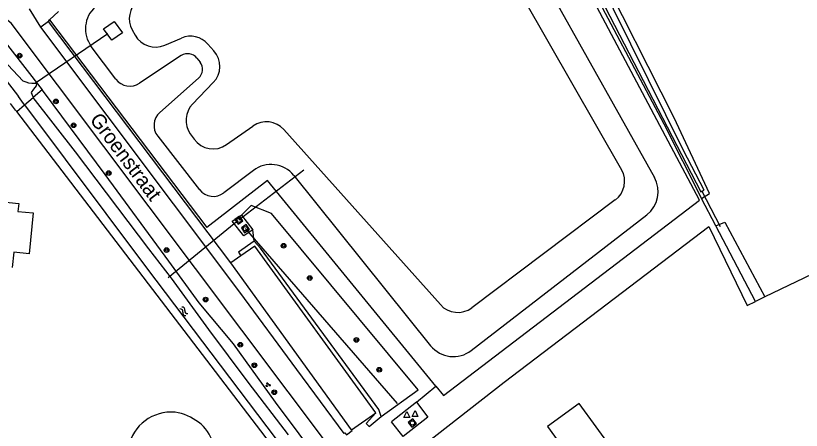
# Model space of a CAD drawing. Extents: x 136000 to 141014, y 402000 to 403500.
# Drawn here: x 137823.8 to 137958.3, y 402938.4 to 403009.4 of the extents above; entities that cross this region are included whole.
import ezdxf

# ---------------------------------------------------------------- set-up
doc = ezdxf.new("R2010")
doc.units = 0
for name, color, linetype in [('gg-afsc-hekwerk', 7, 'Continuous'), ('gg-anno-openbare ruimte label', 7, 'Continuous'), ('gg-bbg-gedigitaliseerde bijgebouw', 7, 'Continuous'), ('gg-bbg-hoofdgebouw', 7, 'Continuous'), ('gg-knt-bronhoudergrens', 7, 'Continuous'), ('gg-knt-verharding', 7, 'Continuous'), ('gg-knt-verharding nz', 7, 'Continuous'), ('gg-kntw-bovenkant insteek waterloop', 7, 'Continuous'), ('gg-kntw-waterlijn', 7, 'Continuous'), ('gg-kwrk-betonelement', 7, 'Continuous'), ('gg-kwrk-duiker nz buis', 7, 'Continuous'), ('gt-grn-groengrens', 7, 'Continuous'), ('gt-grn-vlakafsluiter', 7, 'Continuous'), ('gt-symb-boom', 7, 'Continuous'), ('gt-symb-groenvak', 7, 'Continuous'), ('gt-symb-rioolschacht', 7, 'Continuous'), ('gt-symb-waterafsluiter', 7, 'Continuous'), ('gt-symb-watersymbool', 7, 'Continuous'), ('gx-grn-maaiveld', 7, 'Continuous')]:
    doc.layers.add(name, color=color, linetype=linetype)

# ---------------------------------------------------------------- blocks, each defined once
blk = doc.blocks.new('gt0-RS')
at = {"layer": 'gt-symb-rioolschacht'}
blk.add_lwpolyline([(-0.5, -0.5), (0.5, -0.5), (0.5, 0.5), (-0.5, 0.5)], close=True, dxfattribs=at)
blk.add_circle((0, 0), 0.375, dxfattribs=at)
blk = doc.blocks.new('gt0-BOOM')
at = {"layer": 'gt-symb-boom'}
for radius in [0.4, 0.2]:
    blk.add_circle((0, 0), radius, dxfattribs=at)
blk = doc.blocks.new('gt0-WAFSL')
at = {"layer": 'gt-symb-waterafsluiter'}
for p, q in [((-0.5, -0.33), (0, 0.67)), ((0, 0.67), (0.5, -0.33)), ((0.5, -0.33), (-0.5, -0.33))]:
    blk.add_line(p, q, dxfattribs=at)
blk = doc.blocks.new('gt0-GRVAK')
at = {"layer": 'gt-symb-groenvak'}
for p, q in [((-0.11, 0.19), (-0.23, 0.24)), ((-0.18, 0.15), (0.09, 0.15)), ((-0.09, 0.21), (-0.16, 0.32)), ((-0.05, 0.21), (-0.05, 0.39)), ((0, 0.21), (0.06, 0.32)), ((0.02, 0.19), (0.13, 0.24)), ((0.26, -0.05), (0.2, 0.06)), ((0.31, -0.05), (0.31, 0.13)), ((0.35, -0.05), (0.41, 0.06)), ((-0.24, -0.23), (-0.36, -0.18)), ((-0.32, -0.26), (-0.05, -0.26)), ((-0.23, -0.21), (-0.29, -0.1)), ((-0.18, -0.2), (-0.18, -0.02)), ((-0.14, -0.21), (-0.07, -0.1)), ((-0.12, -0.23), (0, -0.18)), ((0.24, -0.07), (0.12, -0.02)), ((0.17, -0.11), (0.44, -0.11)), ((0.37, -0.07), (0.49, -0.02))]:
    blk.add_line(p, q, dxfattribs=at)
blk = doc.blocks.new('gt0-WA')
at = {"layer": 'gt-symb-watersymbool'}
for centre, start, end in [((-0.32, 0.02), 28.0725, 151.9275), ((0.43, 0.42), 208.0725, 331.9275), ((-0.32, -0.43), 28.0725, 151.9275), ((0.43, -0.03), 208.0725, 331.9275)]:
    blk.add_arc(centre, 0.425, start, end, dxfattribs=at)

msp = doc.modelspace()

# ---------------------------------------------------------------- linework, layer by layer
at = {"layer": 'gg-afsc-hekwerk'}
for p, q in [((137831.1, 403010.12), (137829.58, 403008.71)), ((137829.58, 403008.71), (137856.5, 402973.11)), ((137997.59, 402983.24), (137952.1, 402961.23))]:
    msp.add_line(p, q, dxfattribs=at)
for points in [[(137895.76, 402945.93), (137897.05, 402944.35), (137940.87, 402977.81), (137893.16, 403067.81), (137862.45, 403039.26)], [(137895.76, 402945.93), (137897.05, 402944.35), (137940.87, 402977.81), (137893.16, 403067.81)], [(137895.76, 402945.93), (137866.92, 402981.15), (137856.5, 402973.11)], [(137899.84, 402918.55), (137891.2, 402930.13), (137891.81, 402934.4), (137907.47, 402946.6), (137942.51, 402973.26), (137949.05, 402959.75), (137950.49, 402960.45)]]:
    msp.add_lwpolyline(points, dxfattribs=at)
at = {"layer": 'gg-bbg-gedigitaliseerde bijgebouw'}
msp.add_lwpolyline([(137923.55, 402927.02), (137929, 402930.97), (137920.28, 402942.97), (137914.84, 402939.02), (137923.55, 402927.02)], dxfattribs=at)
at = {"layer": 'gg-bbg-hoofdgebouw'}
msp.add_lwpolyline([(137813.34, 402978.35), (137824.31, 402977.25), (137824.17, 402975.86), (137826.77, 402975.61), (137826.07, 402968.62), (137823.47, 402968.88), (137823.21, 402966.26)], dxfattribs=at)
at = {"layer": 'gg-knt-bronhoudergrens'}
msp.add_line((137943.69, 402973.38), (137941.23, 402978.08), dxfattribs=at)
at = {"layer": 'gg-knt-verharding'}
for p, q in [((137828.07, 403007.44), (137826.13, 403010.6)), ((137829.42, 403008.43), (137828.07, 403007.44)), ((137860.63, 402967.06), (137829.42, 403008.43)), ((137862.45, 402975.22), (137864.4, 402972.7)), ((137862.35, 402968.25), (137860.63, 402967.06)), ((137881.3, 402938.43), (137885.49, 402941.37))]:
    msp.add_line(p, q, dxfattribs=at)
for points in [[(137894.08, 402913.47), (137823.01, 403008.12), (137819.08, 403011.19)], [(137880.03, 402937.81), (137871.91, 402948.77), (137862.18, 402962.01), (137828.07, 403007.44)], [(137864.4, 402972.7), (137862.84, 402971.67), (137860.89, 402974.19), (137862.45, 402975.22)], [(137885.49, 402941.37), (137864.76, 402969.91), (137862.35, 402968.25)], [(137880.03, 402937.81), (137880.18, 402937.9), (137880.42, 402937.59), (137881.4, 402938.3), (137881.3, 402938.43)]]:
    msp.add_lwpolyline(points, dxfattribs=at)
for centre, radius, start, end in [((137850.46, 402933.95), 7.54, 85.1609, 168.2904), ((137849.55, 402932.39), 9.21, 52.8911, 80.3469), ((137851.41, 402934.61), 6.32, 335.93, 54.1755)]:
    msp.add_arc(centre, radius, start, end, dxfattribs=at)
at = {"layer": 'gg-knt-verharding nz'}
msp.add_line((137881.3, 402938.43), (137860.63, 402967.06), dxfattribs=at)
at = {"layer": 'gg-kntw-bovenkant insteek waterloop'}
for p, q in [((137893.62, 403052.23), (137933.18, 402981.7)), ((137840.96, 402998.53), (137836.74, 403004.16)), ((137852.15, 403002.57), (137845.02, 402997.83)), ((137854.83, 403002.14), (137855.36, 403001.47)), ((137855.12, 402998.73), (137848.48, 402992.85)), ((137848.11, 402988.76), (137855.27, 402979.6)), ((137864.49, 402982.9), (137859.45, 402979.06)), ((137871.42, 402982.05), (137894.85, 402952.86)), ((137901.81, 402952.04), (137931.88, 402975.3)), ((137943.69, 402973.38), (137945.21, 402974.02)), ((137945.21, 402974.02), (137952.1, 402961.23)), ((137950.49, 402960.45), (137943.69, 402973.38)), ((137952.1, 402961.23), (137950.49, 402960.45))]:
    msp.add_line(p, q, dxfattribs=at)
for points in [[(137768.67, 403074.73), (137798.24, 403034.83), (137810.17, 403020.19), (137820.15, 403007.16), (137828.35, 402996.71)], [(137941.23, 402978.08), (137942.62, 402978.95), (137936.57, 402991.93), (137923.28, 403018.25), (137907.71, 403047.45)], [(137905.65, 403046.37), (137920.71, 403017.57), (137934.76, 402990.86), (137941.23, 402978.08)], [(137896.04, 402906.3), (137895.34, 402907.18), (137880.44, 402926.92), (137868.26, 402943.19), (137861.12, 402953.16), (137855.2, 402960.18), (137850, 402967.32), (137839.09, 402982.21), (137828.74, 402996.21), (137828.35, 402996.71)], [(137823.96, 402992.98), (137823.78, 402993.21), (137822.88, 402994.39)], [(137923.11, 402868.95), (137923.01, 402868.74), (137922.33, 402868.48), (137921.29, 402868.36), (137911.88, 402880.47), (137905.14, 402889.6), (137899.38, 402896.18), (137894.01, 402902.61), (137888.31, 402908.74), (137823.96, 402992.98)]]:
    msp.add_lwpolyline(points, dxfattribs=at)
for centre, radius, start, end in [((137840.74, 403007.16), 5, 131.3047, 216.846), ((137853.26, 403000.91), 2, 38.2097, 123.6164), ((137853.79, 403000.23), 2, 311.5622, 38.2379), ((137843.36, 403000.34), 3, 216.8757, 303.5595), ((137850.47, 402990.61), 3, 131.5615, 218.0219), ((137867.52, 402978.92), 5, 38.7599, 127.3016), ((137928.82, 402979.25), 5, 307.7257, 29.2794), ((137857.63, 402981.45), 3, 218.0307, 307.2776), ((137898.75, 402955.99), 5, 218.7596, 307.7328)]:
    msp.add_arc(centre, radius, start, end, dxfattribs=at)
at = {"layer": 'gg-kntw-waterlijn'}
for p, q in [((137891.37, 403046.14), (137927.55, 402983.02)), ((137843.75, 403007), (137844.25, 403006.1)), ((137849.32, 403004.37), (137852.16, 403005.58)), ((137856.72, 403004.55), (137857.74, 403003.4)), ((137857.63, 402997.97), (137854.08, 402994.27)), ((137826.8, 402995.39), (137826.79, 402995.4)), ((137859.91, 402987.32), (137864.42, 402990.5)), ((137869.71, 402989.9), (137896.52, 402959.9)), ((137853.69, 402989.19), (137854.33, 402988.28)), ((137926.48, 402977.84), (137901.9, 402959.36))]:
    msp.add_line(p, q, dxfattribs=at)
for points in [[(137763.47, 403078.4), (137768.03, 403073.38), (137780.19, 403057.34), (137821.62, 403001.84), (137825.03, 402998.28), (137825.52, 402998.06), (137826, 402997.89), (137826.56, 402997.88), (137827.19, 402997.84), (137827.34, 402997.72), (137827.27, 402997.38), (137826.85, 402996.82), (137826.45, 402996.24), (137826.67, 402995.67), (137826.77, 402995.43), (137826.79, 402995.4)], [(137761.47, 403076.91), (137769.01, 403067.3), (137824.27, 402995.55)], [(137906.67, 403045.93), (137941.12, 402979.21), (137941.67, 402979.5), (137938.14, 402986.33), (137923.12, 403016.68), (137907.61, 403046.31), (137906.67, 403045.93)], [(137825.32, 402994.15), (137825.15, 402994.37), (137824.27, 402995.55)], [(137870.51, 402937.59), (137863.62, 402946.6), (137856.89, 402955.64), (137850.46, 402964.45), (137846.58, 402969.44), (137834.04, 402986.1), (137826.8, 402995.39)], [(137825.32, 402994.14), (137846.18, 402966.19), (137887.42, 402911.68)]]:
    msp.add_lwpolyline(points, dxfattribs=at)
for centre, start, end in [((137847.25, 403008.94), 130.8887, 209.0545), ((137847.75, 403008.04), 209.0526, 293.1374), ((137853.73, 403001.9), 41.5626, 113.1274), ((137854.75, 403000.74), 316.1178, 41.5594), ((137856.96, 402991.5), 136.1107, 215.1747), ((137866.73, 402987.23), 41.7926, 125.1752), ((137857.6, 402990.59), 215.1941, 305.1819), ((137924.08, 402981.03), 306.93, 29.8177), ((137899.5, 402962.56), 221.7893, 306.9286)]:
    msp.add_arc(centre, 4, start, end, dxfattribs=at)
at = {"layer": 'gg-kwrk-betonelement'}
for p in [(137892.43, 402943.2), (137890.14, 402937.32)]:
    msp.add_line(p, (137888.17, 402939.79), dxfattribs=at)
for points in [[(137838.85, 403007.15), (137840.66, 403008.44), (137842.07, 403006.49), (137840.26, 403005.2), (137838.85, 403007.15)], [(137892.43, 402943.2), (137894.39, 402940.59), (137890.14, 402937.32)]]:
    msp.add_lwpolyline(points, dxfattribs=at)
at = {"layer": 'gg-kwrk-duiker nz buis'}
for p, q in [((137839.57, 403006.29), (137827.19, 402997.84)), ((137862.02, 402974.41), (137873.15, 402983)), ((137941.24, 402979.44), (137944.46, 402973.31)), ((137861.84, 402974.25), (137849.91, 402964.5)), ((137889.19, 402942.93), (137863.12, 402972.96))]:
    msp.add_line(p, q, dxfattribs=at)
at = {"layer": 'gt-grn-groengrens'}
for p, q in [((137864.61, 402970.76), (137864.4, 402972.7)), ((137892.43, 402943.2), (137895.76, 402945.93))]:
    msp.add_line(p, q, dxfattribs=at)
for points in [[(137886.39, 402940.75), (137892.72, 402945.28), (137867.58, 402975.49), (137864.14, 402976.9), (137862.45, 402975.22)], [(137864.61, 402970.76), (137861.92, 402968.87), (137862.35, 402968.25)], [(137886.39, 402940.75), (137885.96, 402941.9), (137865.74, 402969.55), (137864.61, 402970.76)], [(137885.49, 402941.37), (137883.8, 402939.52), (137884.3, 402939.01), (137886.39, 402940.75)]]:
    msp.add_lwpolyline(points, dxfattribs=at)
at = {"layer": 'gt-grn-vlakafsluiter'}
for p, q in [((137829.42, 403008.43), (137829.58, 403008.71)), ((137828.35, 402996.71), (137826.8, 402995.39)), ((137825.32, 402994.15), (137826.79, 402995.4)), ((137823.96, 402992.98), (137825.32, 402994.14))]:
    msp.add_line(p, q, dxfattribs=at)
at = {"layer": 'gx-grn-maaiveld'}
msp.add_line((137825.32, 402994.14), (137825.32, 402994.15), dxfattribs=at)

# ---------------------------------------------------------------- block references
at = {"layer": 'gt-symb-boom'}
for p in [(137824.46, 403002.57), (137830.69, 402994.72), (137833.71, 402990.63), (137839.72, 402982.45), (137849.62, 402969.24), (137869.68, 402969.98), (137874.16, 402964.46), (137856.31, 402960.76), (137862.26, 402953.01), (137882.14, 402953.86), (137864.67, 402949.5), (137886.05, 402948.74), (137868.07, 402944.88)]:
    msp.add_blockref('gt0-BOOM', p, dxfattribs=at)
at = {"layer": 'gt-symb-groenvak'}
msp.add_blockref('gt0-GRVAK', (137866.98, 402946.16), dxfattribs=at)
at = {"layer": 'gt-symb-rioolschacht'}
for p, rotation in [((137862.01, 402974.36), -53.452892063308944), ((137863.13, 402972.91), -56.79784911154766), ((137891.73, 402939.62), 127.91745117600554)]:
    msp.add_blockref('gt0-RS', p, dxfattribs=dict(at, rotation=rotation))
at = {"layer": 'gt-symb-waterafsluiter'}
for p in [(137890.78, 402940.9), (137892.18, 402941.06)]:
    msp.add_blockref('gt0-WAFSL', p, dxfattribs=at)
at = {"layer": 'gt-symb-watersymbool', "rotation": -46.701354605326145}
msp.add_blockref('gt0-WA', (137852.56, 402958.8), dxfattribs=at)

# ---------------------------------------------------------------- texts
at = {"layer": 'gg-anno-openbare ruimte label'}
msp.add_text('Groenstraat', height=2.5, rotation=306.9, dxfattribs=at).set_placement((137836.36, 402991.57))

doc.saveas('drawing.dxf')
